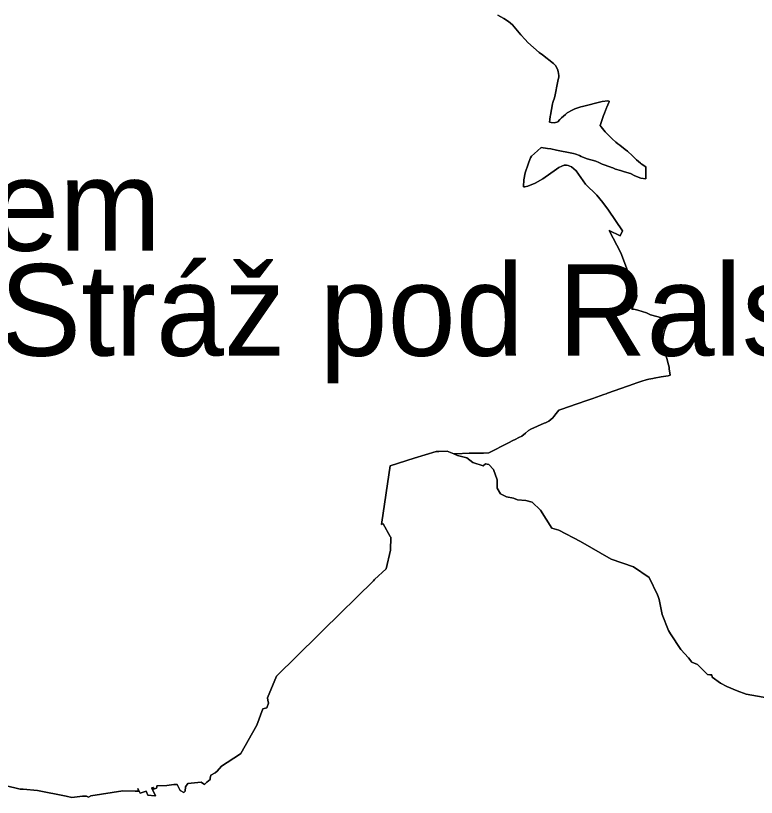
# Model space of a CAD drawing. Extents: x -742239 to -650174, y -1010569 to -945473.
# Drawn here: x -707247 to -703246, y -984820 to -980595 of the extents above; entities that cross this region are included whole.
import ezdxf

# ---------------------------------------------------------------- set-up
doc = ezdxf.new("R2010")
doc.units = 0
doc.layers.add('Hranice obcí', color=7, linetype='Continuous')
doc.layers.add('Obce popis', color=7, linetype='Continuous')

msp = doc.modelspace()

# ---------------------------------------------------------------- linework, layer by layer
at = {"layer": 'Hranice obcí'}
for points in [[(-704643.5, -980593), (-704611, -980609.8), (-704584.7, -980626.4), (-704564, -980644), (-704518.4, -980698.7), (-704494.8, -980724.4), (-704479.8, -980739.6), (-704419.7, -980794.3), (-704402.1, -980806.4), (-704342.3, -980853.9), (-704331.6, -980864.9), (-704320.2, -980884.6), (-704316.3, -980896.2), (-704312.9, -980917.9), (-704313.4, -980926.3), (-704319.3, -980949.3), (-704335.2, -981031.2), (-704338.6, -981044.7), (-704342.2, -981054.3), (-704346.1, -981064.3), (-704347.3, -981071.8), (-704352.5, -981102.5)], [(-704053.2, -981088.9), (-704042.5, -981065), (-704041.4, -981060), (-704040.5, -981056.2), (-704047.5, -981055.6), (-704079.3, -981058.1), (-704184.4, -981086), (-704193.9, -981087.4), (-704200.1, -981089.3), (-704227.5, -981099.2), (-704248.8, -981108.5), (-704261, -981116.4), (-704267.8, -981120.8), (-704277.7, -981128.6), (-704298.9, -981147.4), (-704308, -981157), (-704318.3, -981167.9), (-704323.3, -981170.9), (-704331.4, -981173.1), (-704337.1, -981173.5), (-704353.8, -981172.8), (-704363.3, -981170.6), (-704361.6, -981156.4), (-704360, -981140.2), (-704358.9, -981132.2), (-704352.5, -981102.5), (-704347.3, -981071.8), (-704346.1, -981064.3), (-704342.2, -981054.3), (-704338.6, -981044.7), (-704335.2, -981031.2), (-704319.3, -980949.3), (-704313.4, -980926.3), (-704312.9, -980917.9), (-704316.3, -980896.2), (-704320.2, -980884.6), (-704331.6, -980864.9), (-704342.3, -980853.9), (-704402.1, -980806.4), (-704419.7, -980794.3), (-704479.8, -980739.6), (-704494.8, -980724.4), (-704518.4, -980698.7), (-704564, -980644), (-704584.7, -980626.4), (-704611, -980609.8), (-704643.5, -980593)], [(-704352.5, -981102.5), (-704358.9, -981132.2), (-704360, -981140.2), (-704361.6, -981156.4), (-704363.3, -981170.6), (-704353.8, -981172.8), (-704337.1, -981173.5), (-704331.4, -981173.1), (-704323.3, -981170.9), (-704318.3, -981167.9), (-704308, -981157), (-704298.9, -981147.4), (-704277.7, -981128.6), (-704267.8, -981120.8), (-704261, -981116.4), (-704248.8, -981108.5), (-704227.5, -981099.2), (-704200.1, -981089.3), (-704193.9, -981087.4), (-704184.4, -981086), (-704079.3, -981058.1), (-704047.5, -981055.6), (-704040.5, -981056.2), (-704041.4, -981060), (-704042.5, -981065), (-704053.2, -981088.9), (-704054.8, -981092.5), (-704066.6, -981121.3), (-704071, -981134.3), (-704090, -981188.7), (-704083.5, -981195.4), (-704062, -981222.3), (-704051.1, -981234.5), (-704024.8, -981261), (-704005.7, -981278.7), (-703994.2, -981287.1), (-703984.3, -981294.3), (-703955.4, -981317.9), (-703942, -981328), (-703915.9, -981351.8), (-703898.6, -981368.4), (-703893, -981374.1), (-703872.6, -981391.7), (-703868.1, -981395.5), (-703843.4, -981411.8), (-703842.2, -981434.9), (-703842.9, -981476.4), (-703870.9, -981473.6), (-703901.7, -981460.5), (-703926.4, -981448.9), (-703958.1, -981438.7), (-703980.3, -981432.3), (-704007.7, -981424.3), (-704021.4, -981417.8), (-704028.3, -981415.2), (-704032.5, -981413.5), (-704078.4, -981396.8), (-704088.9, -981392.1), (-704097.3, -981388.5), (-704113.9, -981382.2), (-704160.8, -981369.2), (-704183.8, -981360.5), (-704193.1, -981355.3), (-704202.3, -981351.3), (-704222.1, -981343.1), (-704233.9, -981340.6), (-704243.1, -981338.7), (-704326, -981321.7), (-704357.2, -981315.3), (-704374.4, -981313.6), (-704408.7, -981308.4), (-704428.6, -981325.3), (-704460, -981354.6), (-704465.3, -981362.5), (-704467.1, -981366.9), (-704479.5, -981397.5), (-704494.6, -981444.3), (-704502, -981483.1), (-704502.9, -981496), (-704503.5, -981504.2), (-704503.3, -981515.8), (-704503.3, -981520.8), (-704496.6, -981520.5), (-704479.9, -981516), (-704440.6, -981500.8), (-704399.1, -981477.2), (-704326.4, -981424.8), (-704312.8, -981415.9), (-704297.5, -981408.4), (-704284, -981403.8), (-704271.1, -981402.5), (-704262.1, -981404.2), (-704244.6, -981412), (-704218.9, -981434.2), (-704168.7, -981506.5), (-704107.3, -981565.1), (-704074.7, -981604.1), (-704045.2, -981646.3), (-703968.7, -981758.2), (-703981.5, -981784.5), (-704040.5, -981755.9)], [(-703729.9, -982448), (-703741.7, -982406.8), (-703743.6, -982399.9), (-703749.5, -982372.4), (-703750.8, -982351.8), (-703749.3, -982331.2), (-703746.7, -982312.9), (-703743, -982299), (-703736.5, -982283.3), (-703725.3, -982261.2), (-703715.3, -982240.9), (-703744.6, -982231.2), (-703755.9, -982227.5), (-703818, -982211.7), (-703829.1, -982206.6), (-703840, -982201.6), (-703885.8, -982186.1), (-703907.5, -982181.8), (-703919.2, -982180.9), (-703895.3, -982126.4), (-703893.3, -982120.2), (-703891.7, -982109.4), (-703894.3, -982098.3), (-703898.8, -982087.6), (-703977.6, -981876.1), (-704040.5, -981755.9), (-703981.5, -981784.5), (-703968.7, -981758.2), (-704045.2, -981646.3), (-704074.7, -981604.1), (-704107.3, -981565.1), (-704168.7, -981506.5), (-704218.9, -981434.2), (-704244.6, -981412), (-704262.1, -981404.2), (-704271.1, -981402.5), (-704284, -981403.8), (-704297.5, -981408.4), (-704312.8, -981415.9), (-704326.4, -981424.8), (-704399.1, -981477.2), (-704440.6, -981500.8), (-704479.9, -981516), (-704496.6, -981520.5), (-704503.3, -981520.8), (-704503.3, -981515.8), (-704503.5, -981504.2), (-704502.9, -981496), (-704502, -981483.1), (-704494.6, -981444.3), (-704479.5, -981397.5), (-704467.1, -981366.9), (-704465.3, -981362.5), (-704460, -981354.6), (-704428.6, -981325.3), (-704408.7, -981308.4), (-704374.4, -981313.6), (-704357.2, -981315.3), (-704326, -981321.7), (-704243.1, -981338.7), (-704233.9, -981340.6), (-704222.1, -981343.1), (-704202.3, -981351.3), (-704193.1, -981355.3), (-704183.8, -981360.5), (-704160.8, -981369.2), (-704113.9, -981382.2), (-704097.3, -981388.5), (-704088.9, -981392.1), (-704078.4, -981396.8), (-704032.5, -981413.5), (-704028.3, -981415.2), (-704021.4, -981417.8), (-704007.7, -981424.3), (-703980.3, -981432.3), (-703958.1, -981438.7), (-703926.4, -981448.9), (-703901.7, -981460.5), (-703870.9, -981473.6), (-703842.9, -981476.4), (-703842.2, -981434.9), (-703843.4, -981411.8), (-703868.1, -981395.5), (-703872.6, -981391.7), (-703893, -981374.1), (-703898.6, -981368.4), (-703915.9, -981351.8), (-703942, -981328), (-703955.4, -981317.9), (-703984.3, -981294.3), (-703994.2, -981287.1), (-704005.7, -981278.7), (-704024.8, -981261), (-704051.1, -981234.5), (-704062, -981222.3), (-704083.5, -981195.4), (-704090, -981188.7), (-704071, -981134.3), (-704066.6, -981121.3), (-704054.8, -981092.5), (-704053.2, -981088.9)], [(-704040.5, -981755.9), (-703977.6, -981876.1), (-703898.8, -982087.6), (-703894.3, -982098.3), (-703891.7, -982109.4), (-703893.3, -982120.2), (-703895.3, -982126.4), (-703919.2, -982180.9), (-703907.5, -982181.8), (-703885.8, -982186.1), (-703840, -982201.6), (-703829.1, -982206.6), (-703818, -982211.7), (-703755.9, -982227.5), (-703744.6, -982231.2), (-703715.3, -982240.9), (-703725.3, -982261.2), (-703736.5, -982283.3), (-703743, -982299), (-703746.7, -982312.9), (-703749.3, -982331.2), (-703750.8, -982351.8), (-703749.5, -982372.4), (-703743.6, -982399.9), (-703741.7, -982406.8), (-703729.9, -982448), (-703720.8, -982482.1), (-703717.9, -982495.4), (-703717.1, -982503.1), (-703711.1, -982538.9), (-703723.3, -982541.1), (-703760.5, -982547.8), (-703798.9, -982554.7), (-703805.3, -982555.9), (-703816.3, -982557.9), (-703826, -982559.6), (-703842, -982563.1), (-703864.8, -982570.6), (-703896.7, -982581.9), (-703905.4, -982585.5), (-704049.7, -982635.9), (-704057.9, -982639.1), (-704069.6, -982642.7), (-704128.7, -982663.6), (-704167.6, -982676.8), (-704208.1, -982691.2), (-704230, -982698.4), (-704245, -982703.4), (-704312.9, -982726.9), (-704328.1, -982745.9), (-704339.3, -982761.1), (-704345.7, -982768.8), (-704366.7, -982786.2), (-704385.8, -982795.6), (-704391.8, -982797.9), (-704463.9, -982830.8), (-704476.4, -982836.5), (-704493.4, -982851.5), (-704513, -982867.3), (-704528.5, -982874.7), (-704548.4, -982885.2), (-704562.2, -982891.7), (-704585, -982903.4), (-704691.6, -982958.3), (-704719.7, -982959.6), (-704797.2, -982960.2), (-704871.3, -982963.7), (-704879.9, -982963.8), (-704916.7, -982949.2), (-704961.3, -982950.5), (-704976.2, -982950.1), (-705094.6, -982987), (-705224, -983027.4), (-705268.7, -983332.6), (-705270.5, -983344.6), (-705262.9, -983342.1), (-705223.7, -983410.8), (-705220.8, -983413.7), (-705223.3, -983483.6), (-705245.3, -983584.1), (-705308.1, -983643.2), (-705313.8, -983648.9), (-705585.6, -983916.3), (-705594.9, -983925.6), (-705608.9, -983939.6), (-705613.4, -983944.1), (-705839.1, -984165.1), (-705886.6, -984283), (-705885.9, -984294.6), (-705880.9, -984311.6), (-705890.7, -984335.6), (-705905.4, -984339.3), (-705912.7, -984341.1), (-705945.4, -984429.7), (-706030.5, -984583.3), (-706038.4, -984588.5), (-706134.8, -984652.3), (-706159.1, -984678), (-706168.9, -984688.3), (-706193.2, -984700.4), (-706195.8, -984716.7)], [(-703128.2, -984292.4), (-703301.6, -984263.1), (-703350, -984243.8), (-703405.1, -984220.4), (-703439.4, -984202.4), (-703484, -984170.8), (-703486.8, -984158.5), (-703497.8, -984158), (-703510.1, -984155.6), (-703563.9, -984101.1), (-703595.2, -984090.1), (-703613, -984066.1), (-703653.2, -984021), (-703710.6, -983936.5), (-703721.5, -983918.2), (-703754.1, -983830.8), (-703764.7, -983786.5), (-703770.5, -983750.2), (-703776.3, -983734.5), (-703780.2, -983725.6), (-703824.4, -983631.8), (-703909.2, -983574.2), (-704030.9, -983532), (-704196.4, -983438), (-704313.4, -983375.7), (-704350.3, -983365.8), (-704411.3, -983267.9), (-704456.5, -983223.9), (-704492.1, -983214.8), (-704536.3, -983211.9), (-704557.1, -983202.4), (-704595.3, -983194.9), (-704627.5, -983179.3), (-704646, -983149.4), (-704645.4, -983104.4), (-704665.7, -983048.8), (-704690.8, -983020.4), (-704709.9, -983018), (-704722.6, -983027.5), (-704776.9, -983010.7), (-704810.5, -982984.8), (-704860.4, -982971.5), (-704879.9, -982963.8), (-704871.3, -982963.7), (-704797.2, -982960.2), (-704719.7, -982959.6), (-704691.6, -982958.3), (-704585, -982903.4), (-704562.2, -982891.7), (-704548.4, -982885.2), (-704528.5, -982874.7), (-704513, -982867.3), (-704493.4, -982851.5), (-704476.4, -982836.5), (-704463.9, -982830.8), (-704391.8, -982797.9), (-704385.8, -982795.6), (-704366.7, -982786.2), (-704345.7, -982768.8), (-704339.3, -982761.1), (-704328.1, -982745.9), (-704312.9, -982726.9), (-704245, -982703.4), (-704230, -982698.4), (-704208.1, -982691.2), (-704167.6, -982676.8), (-704128.7, -982663.6), (-704069.6, -982642.7), (-704057.9, -982639.1), (-704049.7, -982635.9), (-703905.4, -982585.5), (-703896.7, -982581.9), (-703864.8, -982570.6), (-703842, -982563.1), (-703826, -982559.6), (-703816.3, -982557.9), (-703805.3, -982555.9), (-703798.9, -982554.7), (-703760.5, -982547.8), (-703723.3, -982541.1), (-703711.1, -982538.9), (-703717.1, -982503.1), (-703717.9, -982495.4), (-703720.8, -982482.1), (-703729.9, -982448)], [(-707303.7, -984756.8), (-707223.5, -984775.1), (-707206.3, -984776.5), (-707128.8, -984782.4), (-706974, -984814.2), (-706944.5, -984820.1), (-706886.8, -984813.1), (-706864.7, -984812.9), (-706853.6, -984819), (-706842, -984812.6), (-706668.6, -984784.4), (-706602.3, -984786.2), (-706584.6, -984786.4), (-706588.2, -984772.3), (-706575.1, -984796.8), (-706542.4, -984786.8), (-706533.3, -984807.8), (-706495.3, -984812.2), (-706493.1, -984812.5), (-706491.1, -984812.7), (-706512.3, -984769.7), (-706512.9, -984768.3), (-706505.1, -984767.2), (-706503.1, -984766.9), (-706502.2, -984775.1), (-706486.2, -984771.2), (-706485.3, -984764.4), (-706484.4, -984757.7), (-706431, -984755.6), (-706393.4, -984751.3), (-706374.4, -984750.8), (-706358.6, -984782.2), (-706339.3, -984793.2), (-706332.3, -984787.4), (-706329.6, -984764), (-706316.8, -984745.6), (-706245.9, -984737.8), (-706227, -984750.2), (-706215.5, -984738.5), (-706196.9, -984723.6), (-706195.8, -984716.7), (-706193.2, -984700.4), (-706168.9, -984688.3), (-706159.1, -984678), (-706134.8, -984652.3), (-706038.4, -984588.5), (-706030.5, -984583.3), (-705945.4, -984429.7), (-705912.7, -984341.1), (-705905.4, -984339.3), (-705890.7, -984335.6), (-705880.9, -984311.6), (-705885.9, -984294.6), (-705886.6, -984283), (-705839.1, -984165.1), (-705613.4, -983944.1), (-705608.9, -983939.6), (-705594.9, -983925.6), (-705585.6, -983916.3), (-705313.8, -983648.9), (-705308.1, -983643.2), (-705245.3, -983584.1), (-705223.3, -983483.6), (-705220.8, -983413.7), (-705223.7, -983410.8), (-705262.9, -983342.1), (-705270.5, -983344.6), (-705268.7, -983332.6), (-705224, -983027.4), (-705094.6, -982987), (-704976.2, -982950.1), (-704961.3, -982950.5), (-704916.7, -982949.2), (-704879.9, -982963.8), (-704860.4, -982971.5), (-704810.5, -982984.8), (-704776.9, -983010.7), (-704722.6, -983027.5), (-704709.9, -983018), (-704690.8, -983020.4), (-704665.7, -983048.8), (-704645.4, -983104.4), (-704646, -983149.4), (-704627.5, -983179.3), (-704595.3, -983194.9), (-704557.1, -983202.4), (-704536.3, -983211.9), (-704492.1, -983214.8), (-704456.5, -983223.9)], [(-704456.5, -983223.9), (-704411.3, -983267.9), (-704350.3, -983365.8), (-704313.4, -983375.7), (-704196.4, -983438), (-704030.9, -983532), (-703909.2, -983574.2), (-703824.4, -983631.8), (-703780.2, -983725.6), (-703776.3, -983734.5), (-703770.5, -983750.2), (-703764.7, -983786.5), (-703754.1, -983830.8), (-703721.5, -983918.2), (-703710.6, -983936.5), (-703653.2, -984021), (-703613, -984066.1), (-703595.2, -984090.1), (-703563.9, -984101.1), (-703510.1, -984155.6), (-703497.8, -984158), (-703486.8, -984158.5), (-703484, -984170.8), (-703439.4, -984202.4), (-703405.1, -984220.4), (-703350, -984243.8), (-703301.6, -984263.1), (-703128.2, -984292.4)], [(-706195.8, -984716.7), (-706196.9, -984723.6), (-706215.5, -984738.5), (-706227, -984750.2), (-706245.9, -984737.8), (-706316.8, -984745.6), (-706329.6, -984764), (-706332.3, -984787.4), (-706339.3, -984793.2), (-706358.6, -984782.2), (-706374.4, -984750.8), (-706393.4, -984751.3), (-706431, -984755.6), (-706484.4, -984757.7), (-706485.3, -984764.4), (-706486.2, -984771.2), (-706502.2, -984775.1), (-706503.1, -984766.9), (-706505.1, -984767.2), (-706512.9, -984768.3), (-706512.3, -984769.7), (-706491.1, -984812.7), (-706493.1, -984812.5), (-706495.3, -984812.2), (-706533.3, -984807.8), (-706542.4, -984786.8), (-706575.1, -984796.8), (-706588.2, -984772.3), (-706584.6, -984786.4), (-706602.3, -984786.2), (-706668.6, -984784.4), (-706842, -984812.6), (-706853.6, -984819), (-706864.7, -984812.9), (-706886.8, -984813.1), (-706944.5, -984820.1), (-706974, -984814.2), (-707128.8, -984782.4), (-707206.3, -984776.5), (-707223.5, -984775.1), (-707303.7, -984756.8)]]:
    msp.add_lwpolyline(points, dxfattribs=at)

# ---------------------------------------------------------------- texts
at = {"layer": 'Obce popis'}
for s, p in [('pod Ralskem', (-710324.2, -981865.7)), ('Stráž pod Ralskem', (-707335.1, -982433.1))]:
    msp.add_text(s, height=495, dxfattribs=at).set_placement(p)

doc.saveas('drawing.dxf')
